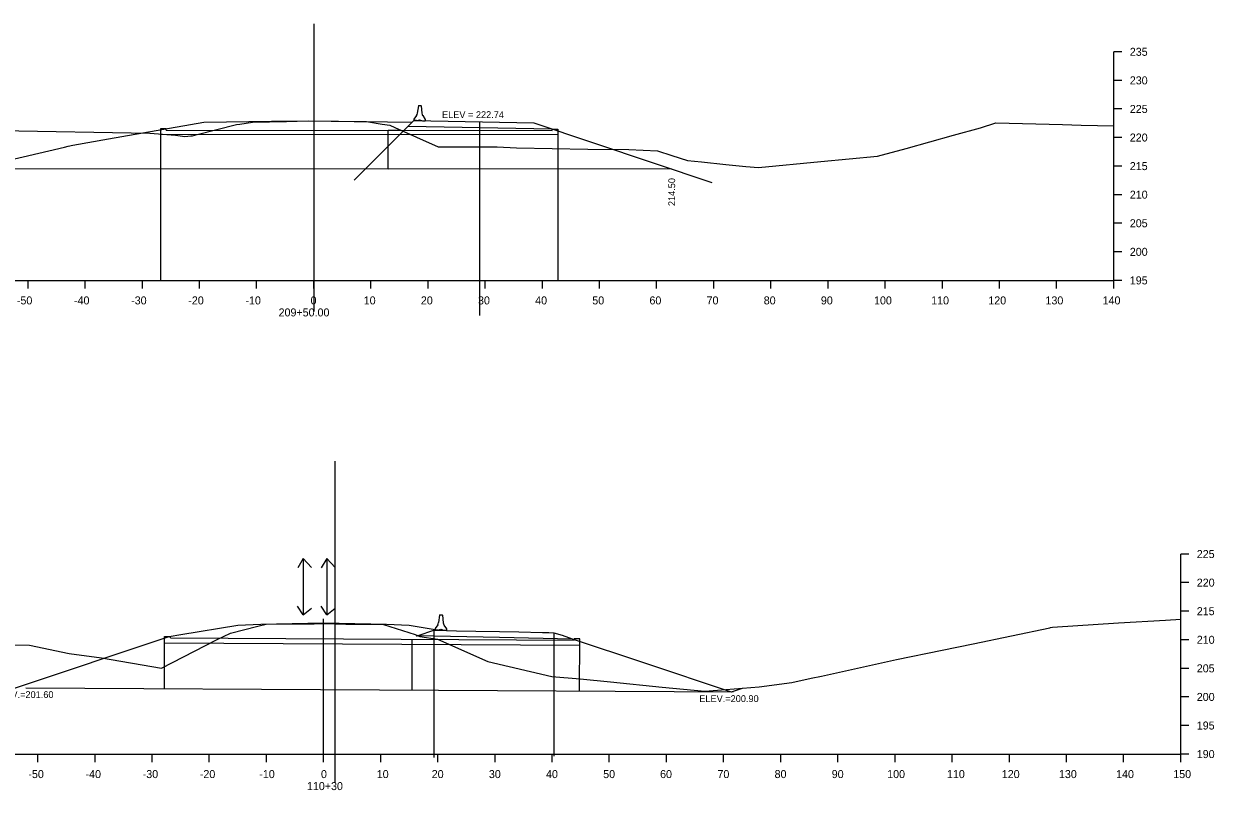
# Model space of a CAD drawing. Extents: x 2829243 to 2838161, y 467639 to 474695.
# Drawn here: x 2831905 to 2832947, y 468831 to 469501 of the extents above; entities that cross this region are included whole.
import ezdxf

# ---------------------------------------------------------------- set-up
doc = ezdxf.new("R2010")
doc.units = 0
for name, color, linetype in [('Default', 7, 'Continuous'), ('R_Alt Surface', 7, 'Continuous'), ('R_Axis', 7, 'Continuous'), ('R_Axis Annot', 7, 'Continuous'), ('R_Detour', 7, 'Continuous'), ('R_Dimension', 7, 'Continuous'), ('R_Exist Surface', 7, 'Continuous'), ('R_Fin Surface', 7, 'Continuous'), ('R_Grid', 7, 'Continuous'), ('R_MOT', 7, 'Continuous'), ('R_Water', 7, 'Continuous'), ('R_Xsect Elev', 7, 'Continuous')]:
    doc.layers.add(name, color=color, linetype=linetype)

msp = doc.modelspace()

# ---------------------------------------------------------------- linework, layer by layer
at = {"layer": 'Default'}
for p, q in [((2832025, 469374.7), (2832025, 469276.8)), ((2832372.7, 469374.4), (2832372.7, 469276.8))]:
    msp.add_line(p, q, dxfattribs=at)
at = {"layer": 'R_Alt Surface'}
msp.add_lwpolyline([(2832250, 468966), (2832321.6, 468964.6), (2832385.1, 468963.3)], dxfattribs=at)
at = {"layer": 'R_Axis'}
for p, q in [((2832859.1, 469276.8), (2832859.1, 469476.8)), ((2832866.1, 469476.8), (2832859.1, 469476.8)), ((2832866.1, 469451.8), (2832859.1, 469451.8)), ((2832866.1, 469426.8), (2832859.1, 469426.8)), ((2832866.1, 469401.8), (2832859.1, 469401.8)), ((2832866.1, 469376.8), (2832859.1, 469376.8)), ((2832866.1, 469351.8), (2832859.1, 469351.8)), ((2832866.1, 469326.8), (2832859.1, 469326.8)), ((2832866.1, 469301.8), (2832859.1, 469301.8)), ((2831459.1, 469276.8), (2832859.1, 469276.8)), ((2831909.1, 469269.8), (2831909.1, 469276.8)), ((2831959.1, 469269.8), (2831959.1, 469276.8)), ((2832009.1, 469269.8), (2832009.1, 469276.8)), ((2832059.1, 469269.8), (2832059.1, 469276.8)), ((2832109.1, 469269.8), (2832109.1, 469276.8)), ((2832159.1, 469269.8), (2832159.1, 469276.8)), ((2832209.1, 469269.8), (2832209.1, 469276.8)), ((2832259.1, 469269.8), (2832259.1, 469276.8)), ((2832309.1, 469269.8), (2832309.1, 469276.8)), ((2832359.1, 469269.8), (2832359.1, 469276.8)), ((2832409.1, 469269.8), (2832409.1, 469276.8)), ((2832459.1, 469269.8), (2832459.1, 469276.8)), ((2832509.1, 469269.8), (2832509.1, 469276.8)), ((2832559.1, 469269.8), (2832559.1, 469276.8)), ((2832609.1, 469269.8), (2832609.1, 469276.8)), ((2832659.1, 469269.8), (2832659.1, 469276.8)), ((2832709.1, 469269.8), (2832709.1, 469276.8)), ((2832759.1, 469269.8), (2832759.1, 469276.8)), ((2832809.1, 469269.8), (2832809.1, 469276.8)), ((2832859.1, 469269.8), (2832859.1, 469276.8)), ((2832866.1, 469276.8), (2832859.1, 469276.8)), ((2832917.7, 468862.4), (2832917.7, 469037.4)), ((2832924.7, 469037.4), (2832917.7, 469037.4)), ((2832924.7, 469012.4), (2832917.7, 469012.4)), ((2832924.7, 468987.4), (2832917.7, 468987.4)), ((2832924.7, 468962.4), (2832917.7, 468962.4)), ((2832924.7, 468937.4), (2832917.7, 468937.4)), ((2832924.7, 468912.4), (2832917.7, 468912.4)), ((2832924.7, 468887.4), (2832917.7, 468887.4)), ((2831417.7, 468862.4), (2832917.7, 468862.4)), ((2831917.7, 468855.4), (2831917.7, 468862.4)), ((2831967.7, 468855.4), (2831967.7, 468862.4)), ((2832017.7, 468855.4), (2832017.7, 468862.4)), ((2832067.7, 468855.4), (2832067.7, 468862.4)), ((2832117.7, 468855.4), (2832117.7, 468862.4)), ((2832167.7, 468855.4), (2832167.7, 468862.4)), ((2832217.7, 468855.4), (2832217.7, 468862.4)), ((2832267.7, 468855.4), (2832267.7, 468862.4)), ((2832317.7, 468855.4), (2832317.7, 468862.4)), ((2832367.7, 468855.4), (2832367.7, 468862.4)), ((2832417.7, 468855.4), (2832417.7, 468862.4)), ((2832467.7, 468855.4), (2832467.7, 468862.4)), ((2832517.7, 468855.4), (2832517.7, 468862.4)), ((2832567.7, 468855.4), (2832567.7, 468862.4)), ((2832617.7, 468855.4), (2832617.7, 468862.4)), ((2832667.7, 468855.4), (2832667.7, 468862.4)), ((2832717.7, 468855.4), (2832717.7, 468862.4)), ((2832767.7, 468855.4), (2832767.7, 468862.4)), ((2832817.7, 468855.4), (2832817.7, 468862.4)), ((2832867.7, 468855.4), (2832867.7, 468862.4)), ((2832917.7, 468855.4), (2832917.7, 468862.4)), ((2832924.7, 468862.4), (2832917.7, 468862.4))]:
    msp.add_line(p, q, dxfattribs=at)
at = {"layer": 'R_Detour'}
msp.add_lwpolyline([(2832249, 468965.7), (2832249.9, 468966), (2832250, 468966), (2832250.4, 468966.1), (2832264.1, 468970.7), (2832275.2, 468970.5), (2832284.1, 468970.3), (2832301, 468970), (2832321.6, 468969.6), (2832338.5, 468969.3), (2832359.1, 468968.8), (2832364.7, 468968.7), (2832369.1, 468968.6), (2832376.3, 468966.3), (2832385.1, 468963.3), (2832447.5, 468942.5), (2832524.4, 468916.9), (2832524.5, 468916.9), (2832534.2, 468920.2)], dxfattribs=at)
at = {"layer": 'R_Dimension'}
for p, q in [((2832524.3, 468916.9), (2832524.4, 468916.9)), ((2832524.4, 468916.9), (2832524.3, 468916.9)), ((2832524.4, 468916.9), (2832524.4, 468916.9)), ((2832524.4, 468916.9), (2832524.4, 468916.9))]:
    msp.add_line(p, q, dxfattribs=at)
msp.add_lwpolyline([(2832524.4, 468916.9), (2832524.4, 468916.9)], dxfattribs=at)
msp.add_lwpolyline([(2832524.4, 468916.9), (2832524.4, 468916.9)], dxfattribs=at)
at = {"layer": 'R_Exist Surface'}
for points in [[(2831884.6, 469408), (2832015.7, 469405.7), (2832038.1, 469403.9), (2832046.2, 469402.6), (2832051.5, 469403.2), (2832053, 469403.2), (2832057.1, 469404.5), (2832091.5, 469413.1), (2832094.3, 469413.6), (2832105.6, 469415.3), (2832135.1, 469415.9), (2832154.1, 469416.4), (2832194.4, 469415.8), (2832205.1, 469415.7), (2832218.9, 469413.6), (2832225.5, 469412.5), (2832229.9, 469410.7), (2832268, 469393.7), (2832280.8, 469393.8), (2832319.5, 469393.8), (2832336.4, 469392.9), (2832398.9, 469391.6), (2832434.7, 469391.4), (2832459.9, 469390.3), (2832472.5, 469386.1), (2832486, 469381.8), (2832498.4, 469380.4), (2832519.6, 469378.3), (2832537.1, 469376.5), (2832548.3, 469375.6), (2832602.8, 469380.8), (2832652.4, 469385.5), (2832677.5, 469392.1), (2832718.7, 469403.9), (2832742.4, 469410.4), (2832756, 469414.6), (2832814.3, 469413.3), (2832830.4, 469412.7), (2832859.1, 469412)], [(2831826.6, 468958.5), (2831910.3, 468957.8), (2831945.1, 468950.4), (2831973.3, 468946.5), (2832025.9, 468937.5), (2832074, 468962.4), (2832086.1, 468968.1), (2832110.2, 468974.4), (2832117.3, 468976.1), (2832159.5, 468976.3), (2832168.3, 468976.5), (2832187.2, 468976.1), (2832220.2, 468975.8), (2832247.8, 468966.9), (2832251.8, 468965.2), (2832267.4, 468962.9), (2832311.3, 468943.4), (2832367.4, 468930.4), (2832392.2, 468928.3), (2832418.8, 468925.6), (2832464, 468920.9), (2832501.2, 468917.3), (2832512.2, 468918.2), (2832548.9, 468921.2), (2832577.4, 468925.1), (2832594.4, 468928.8), (2832603.3, 468930.7), (2832668.9, 468945), (2832708.9, 468953.3), (2832736, 468958.8), (2832803.1, 468972.9), (2832803.8, 468973.1), (2832805.5, 468973.4), (2832863.3, 468977.1), (2832904.3, 468979.6), (2832917.7, 468980.5)]]:
    msp.add_lwpolyline(points, dxfattribs=at)
at = {"layer": 'R_Fin Surface'}
for points in [[(2831835.1, 469379.4), (2831847, 469376.7), (2831858.3, 469374), (2831865.1, 469375.6), (2831870.4, 469376.9), (2831904.7, 469384.9), (2831941.1, 469393.4), (2831944.2, 469394.2), (2831948.2, 469395.1), (2831979.4, 469400.6), (2832063, 469415.3)], [(2832063, 469415.3), (2832122, 469416), (2832159.1, 469416.5), (2832245.1, 469415.2)], [(2831897.2, 468920), (2832032.7, 468965.2), (2832042.9, 468966.9), (2832092.7, 468975.2)], [(2832092.7, 468975.2), (2832112.7, 468976)], [(2832112.7, 468976), (2832167.7, 468977.1), (2832222.7, 468976)], [(2832222.7, 468976), (2832242.7, 468975.2)], [(2832242.7, 468975.2), (2832265.2, 468971.4)]]:
    msp.add_lwpolyline(points, dxfattribs=at)
at = {"layer": 'R_Grid'}
for p, q in [((2832859.1, 469276.8), (2832859.1, 469476.8)), ((2831459.1, 469276.8), (2832859.1, 469276.8)), ((2832917.7, 468862.4), (2832917.7, 469037.4)), ((2831417.7, 468862.4), (2832917.7, 468862.4))]:
    msp.add_line(p, q, dxfattribs=at)
at = {"layer": 'R_MOT'}
for p, q in [((2832249, 469421.2), (2832246.6, 469417.9)), ((2832250.6, 469429.6), (2832249.7, 469423.1)), ((2832250.6, 469429.6), (2832250.9, 469429.9)), ((2832250.9, 469429.9), (2832252.8, 469429.9)), ((2832252.8, 469429.9), (2832253.1, 469429.6)), ((2832253.1, 469429.6), (2832253.7, 469423)), ((2832254.4, 469421.1), (2832256.6, 469417.7)), ((2832246.6, 469417.9), (2832246.6, 469416.7)), ((2832249.1, 469416.6), (2832246.6, 469416.7)), ((2832249.1, 469416.6), (2832251.6, 469417.4)), ((2832251.6, 469417.4), (2832254.1, 469416.5)), ((2832254.1, 469416.5), (2832256.6, 469416.5)), ((2832256.6, 469417.7), (2832256.6, 469416.5)), ((2832269.2, 468983.9), (2832268.3, 468977.4)), ((2832269.2, 468983.9), (2832269.5, 468984.2)), ((2832269.5, 468984.2), (2832271.4, 468984.2)), ((2832271.4, 468984.2), (2832271.7, 468983.9)), ((2832271.7, 468983.9), (2832272.3, 468977.3)), ((2832167.7, 468862.4), (2832167.7, 468980.7)), ((2832267.6, 468975.4), (2832265.2, 468972.2)), ((2832273, 468975.3), (2832275.2, 468972)), ((2832264.1, 468970.7), (2832264.1, 468859.3)), ((2832265.2, 468972.2), (2832265.2, 468971)), ((2832267.7, 468970.9), (2832265.2, 468971)), ((2832267.7, 468970.9), (2832270.2, 468971.7)), ((2832270.2, 468971.7), (2832272.7, 468970.8)), ((2832272.7, 468970.8), (2832275.2, 468970.8)), ((2832275.2, 468972), (2832275.2, 468970.8)), ((2832369.1, 468968.6), (2832369.1, 468860.7))]:
    msp.add_line(p, q, dxfattribs=at)
for centre, start, end in [((2832245.6, 469423.6), 323.8622, 352.8452), ((2832257.8, 469423.4), 184.8632, 213.8462), ((2832264.2, 468977.9), 323.8622, 352.8452), ((2832276.4, 468977.7), 184.8632, 213.8462)]:
    msp.add_arc(centre, 4.17, start, end, dxfattribs=at)
at = {"layer": 'R_Water'}
for p, q in [((2832159.1, 469501.3), (2832159.1, 469249.7)), ((2832246.6, 469416.7), (2832194.3, 469364.4)), ((2832241.7, 469411.8), (2832367.5, 469409.3)), ((2832246.6, 469416.7), (2832351.6, 469414.6)), ((2832304.1, 469415.5), (2832304.1, 469246)), ((2832351.6, 469414.6), (2832507.4, 469362.6)), ((2832025, 469404.7), (2832372.7, 469404.4)), ((2832030, 469408.2), (2832030, 469409.5)), ((2832030, 469408.2), (2832367.7, 469407.9)), ((2832224.1, 469374.5), (2832224.1, 469408.1)), ((2832224.1, 469408.1), (2832234.1, 469408.1)), ((2832367.7, 469407.9), (2832367.7, 469409.2)), ((2831866.9, 469374.8), (2832472.3, 469374.3)), ((2832159.1, 469374.6), (2832224.1, 469374.5)), ((2832177.7, 468837.3), (2832177.7, 469118.6)), ((2832149.9, 469033.6), (2832145.1, 469025.2)), ((2832149.9, 469033.6), (2832149.9, 468984.3)), ((2832149.9, 469033.6), (2832157.1, 469025.6)), ((2832170.5, 469033.6), (2832165.7, 469025.2)), ((2832170.5, 469033.6), (2832170.5, 468984.3)), ((2832170.5, 469033.6), (2832177.8, 469025.6)), ((2832149.9, 468984.3), (2832144.9, 468991.8)), ((2832149.9, 468984.3), (2832157.1, 468990)), ((2832170.5, 468984.3), (2832165.5, 468991.8)), ((2832170.5, 468984.3), (2832177.8, 468990)), ((2832028.4, 468919.7), (2832028.6, 468965.3)), ((2832028.6, 468965.3), (2832033.6, 468965.3)), ((2832033.6, 468964.1), (2832033.6, 468965.3)), ((2832033.6, 468964.1), (2832386.8, 468962.1)), ((2832245.2, 468918.5), (2832245.2, 468962.9)), ((2832386.8, 468962.1), (2832386.8, 468963.3)), ((2832391.8, 468963.3), (2832386.8, 468963.3)), ((2832391.5, 468917.7), (2832391.8, 468963.3)), ((2832028.6, 468959.7), (2832391.8, 468957.7)), ((2831907.2, 468920.4), (2832526, 468916.9))]:
    msp.add_line(p, q, dxfattribs=at)
for points in [[(2832030, 469409.5), (2832025, 469409.5), (2832025, 469374.7)], [(2832367.7, 469409.2), (2832372.7, 469409.2), (2832372.7, 469374.4)]]:
    msp.add_lwpolyline(points, dxfattribs=at)

# ---------------------------------------------------------------- texts
at = {"layer": 'R_Axis Annot'}
for s, p in [('235', (2832873.1, 469473.3)), ('230', (2832873.1, 469448.3)), ('225', (2832873.1, 469423.3)), ('220', (2832873.1, 469398.3)), ('215', (2832873.1, 469373.3)), ('210', (2832873.1, 469348.3)), ('205', (2832873.1, 469323.3)), ('200', (2832873.1, 469298.3)), ('195', (2832873.1, 469273.3)), ('-50', (2831899.3, 469255.8)), ('-40', (2831949.3, 469255.8)), ('-30', (2831999.3, 469255.8)), ('-20', (2832049.3, 469255.8)), ('-10', (2832099.3, 469255.8)), ('0', (2832156.3, 469255.8)), ('10', (2832202.8, 469255.8)), ('20', (2832252.8, 469255.8)), ('30', (2832302.8, 469255.8)), ('40', (2832352.8, 469255.8)), ('50', (2832402.8, 469255.8)), ('60', (2832452.8, 469255.8)), ('70', (2832502.8, 469255.8)), ('80', (2832552.8, 469255.8)), ('90', (2832602.8, 469255.8)), ('100', (2832649.3, 469255.8)), ('110', (2832699.3, 469255.8)), ('120', (2832749.3, 469255.8)), ('130', (2832799.3, 469255.8)), ('140', (2832849.3, 469255.8)), ('209+50.00', (2832128.3, 469245.3)), ('225', (2832931.7, 469033.9)), ('220', (2832931.7, 469008.9)), ('215', (2832931.7, 468983.9)), ('210', (2832931.7, 468958.9)), ('205', (2832931.7, 468933.9)), ('200', (2832931.7, 468908.9)), ('195', (2832931.7, 468883.9)), ('190', (2832931.7, 468858.9)), ('-50', (2831909.4, 468841.4)), ('-40', (2831959.4, 468841.4)), ('-30', (2832009.4, 468841.4)), ('-20', (2832059.4, 468841.4)), ('-10', (2832111.4, 468841.4)), ('0', (2832165.4, 468841.4)), ('10', (2832214.2, 468841.4)), ('20', (2832262.3, 468841.4)), ('30', (2832312.3, 468841.4)), ('40', (2832362.3, 468841.4)), ('50', (2832412.3, 468841.4)), ('60', (2832462.1, 468841.4)), ('70', (2832512.3, 468841.4)), ('80', (2832562.3, 468841.4)), ('90', (2832612.3, 468841.4)), ('100', (2832660.8, 468841.4)), ('110', (2832713.1, 468841.4)), ('120', (2832761.1, 468841.4)), ('130', (2832811.1, 468841.4)), ('140', (2832861.1, 468841.4)), ('150', (2832911.1, 468841.4)), ('110+30', (2832153.1, 468830.9))]:
    msp.add_text(s, height=7, dxfattribs=at).set_placement(p)
at = {"layer": 'R_MOT'}
for p in [(2832246.6, 469416.7), (2832265.2, 468971)]:
    msp.add_text('DWB 1-14-10', height=0.02, rotation=88.8542, dxfattribs=at).set_placement(p)
at = {"layer": 'R_Xsect Elev'}
for s, p in [('ELEV = 222.74', (2832271.3, 469418.8)), ('ELEV.=201.60', (2831879.4, 468911.4)), ('ELEV.=200.90', (2832496.4, 468907.9))]:
    msp.add_text(s, height=6, dxfattribs=at).set_placement(p)
msp.add_text('214.50', height=6, rotation=90, dxfattribs=at).set_placement((2832475.3, 469341.8))

doc.saveas('drawing.dxf')
